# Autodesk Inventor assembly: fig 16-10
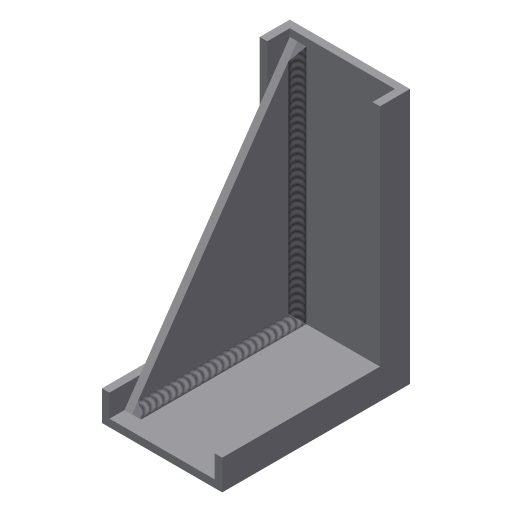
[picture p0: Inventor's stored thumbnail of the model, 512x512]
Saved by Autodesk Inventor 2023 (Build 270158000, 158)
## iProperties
Created: 2003-01
Part Number: fig 16-10
Document SubType Name: Weldment
Designer: Owner
Control State: 0
Master: False
Checked Out: False
Shininess: 64.0
Length Units: 11269
Angle Units: 11279
Time Units: 11290
Mass Units: 11283
Length Display Precision: 3
Angle Display Precision: 2
Compacted: True
Density: 0.0
Volumn: 0.0
Area: 0.0
PropertySet Name: Model Information
Author: Owner
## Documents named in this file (3)
- D:\PROJECTS\Project 2022\Autodesk Inventor For Professional 2023\RESOURCES INVENTOR 2023\RESOURCES INVENTOR 2023\Inventor_2023_Part\Inventor_2023_Part\c16_Inv_2023_prt\fig 16-10\fig 16-10.iam
- D:\PROJECTS\Project 2022\Autodesk Inventor For Professional 2023\RESOURCES INVENTOR 2023\RESOURCES INVENTOR 2023\Inventor_2023_Part\Inventor_2023_Part\c16_Inv_2023_prt\fig 16-10\Bracket-1.ipt
- D:\PROJECTS\Project 2022\Autodesk Inventor For Professional 2023\RESOURCES INVENTOR 2023\RESOURCES INVENTOR 2023\Inventor_2023_Part\Inventor_2023_Part\c16_Inv_2023_prt\fig 16-10\Bracket-plate.ipt
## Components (2 placed, 2 different names)
1. Bracket-1:1 — Mate:1, Mate:2
2. Bracket-plate:1 — Mate:1, Mate:2
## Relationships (2: Mate 2)
- Mate:1: Bracket-1:1 ↔ Bracket-plate:1
- Mate:2: Bracket-1:1 ↔ Bracket-plate:1
